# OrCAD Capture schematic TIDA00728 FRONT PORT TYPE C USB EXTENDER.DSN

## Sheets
1 PAGE4: size C; title: Power; rev: A; note: TIDA00728
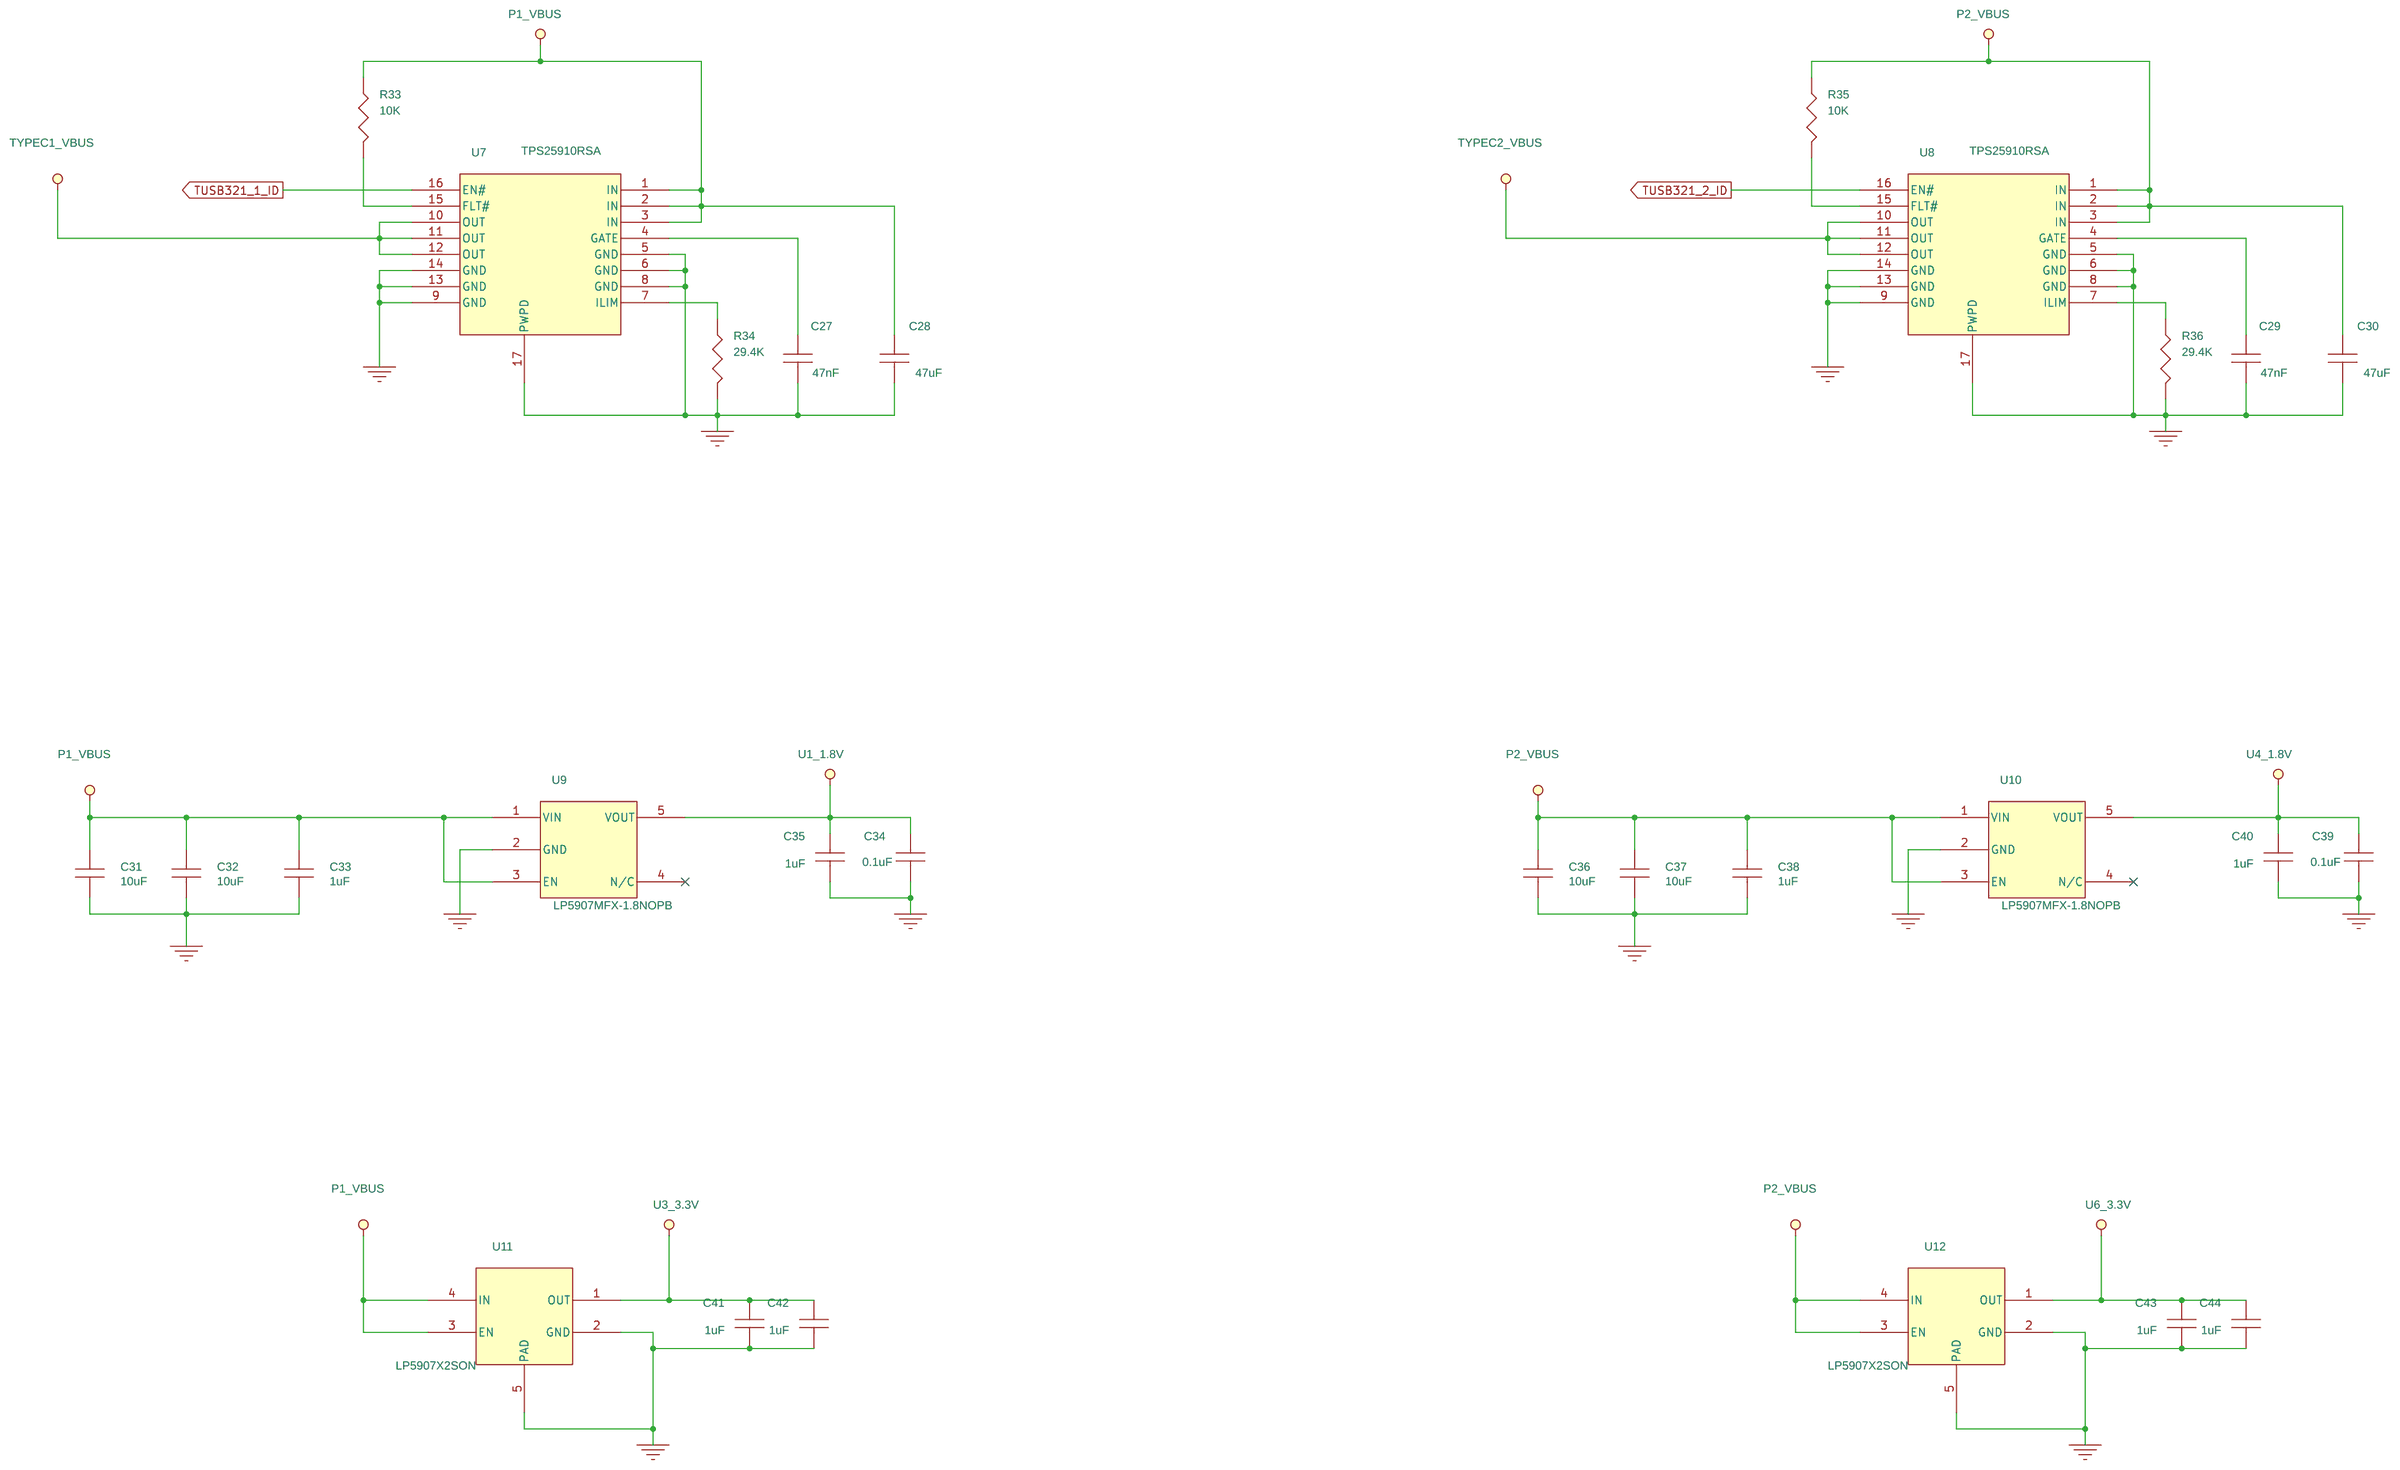
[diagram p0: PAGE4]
2 PAGE3: size C; title: Type C #2
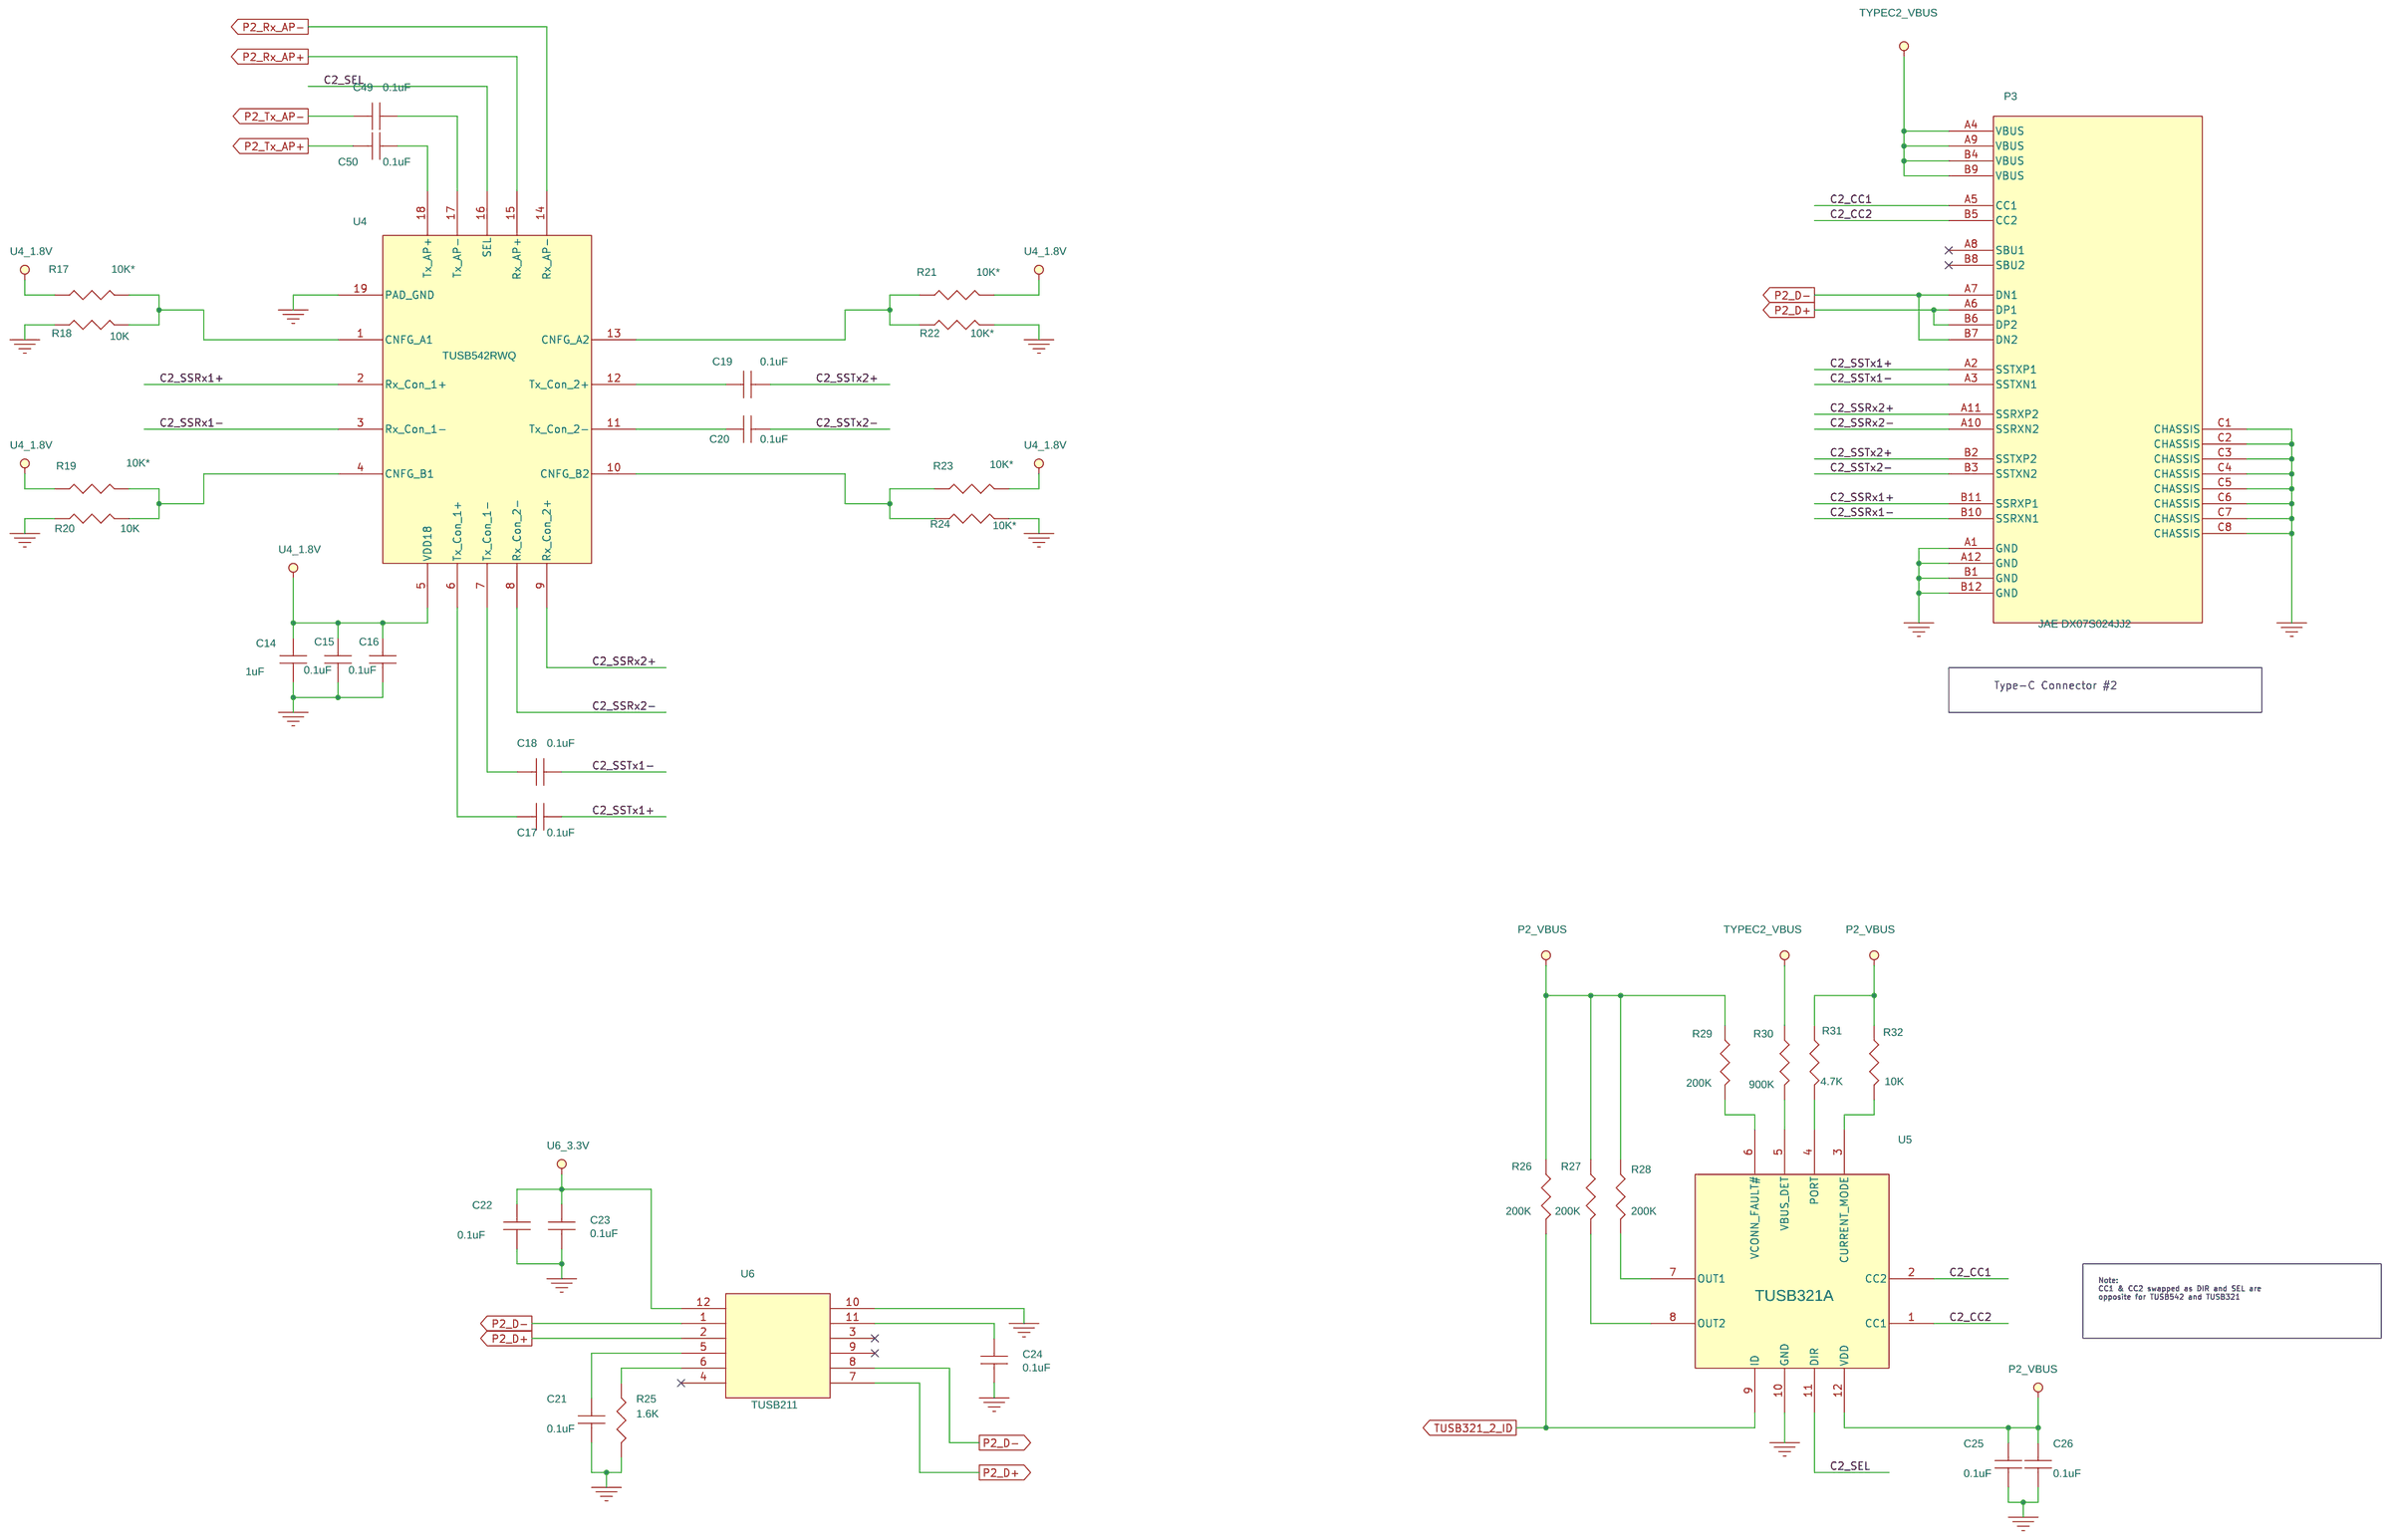
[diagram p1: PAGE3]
3 PAGE2: size C; title: Daughter Card Header + TypeC #1
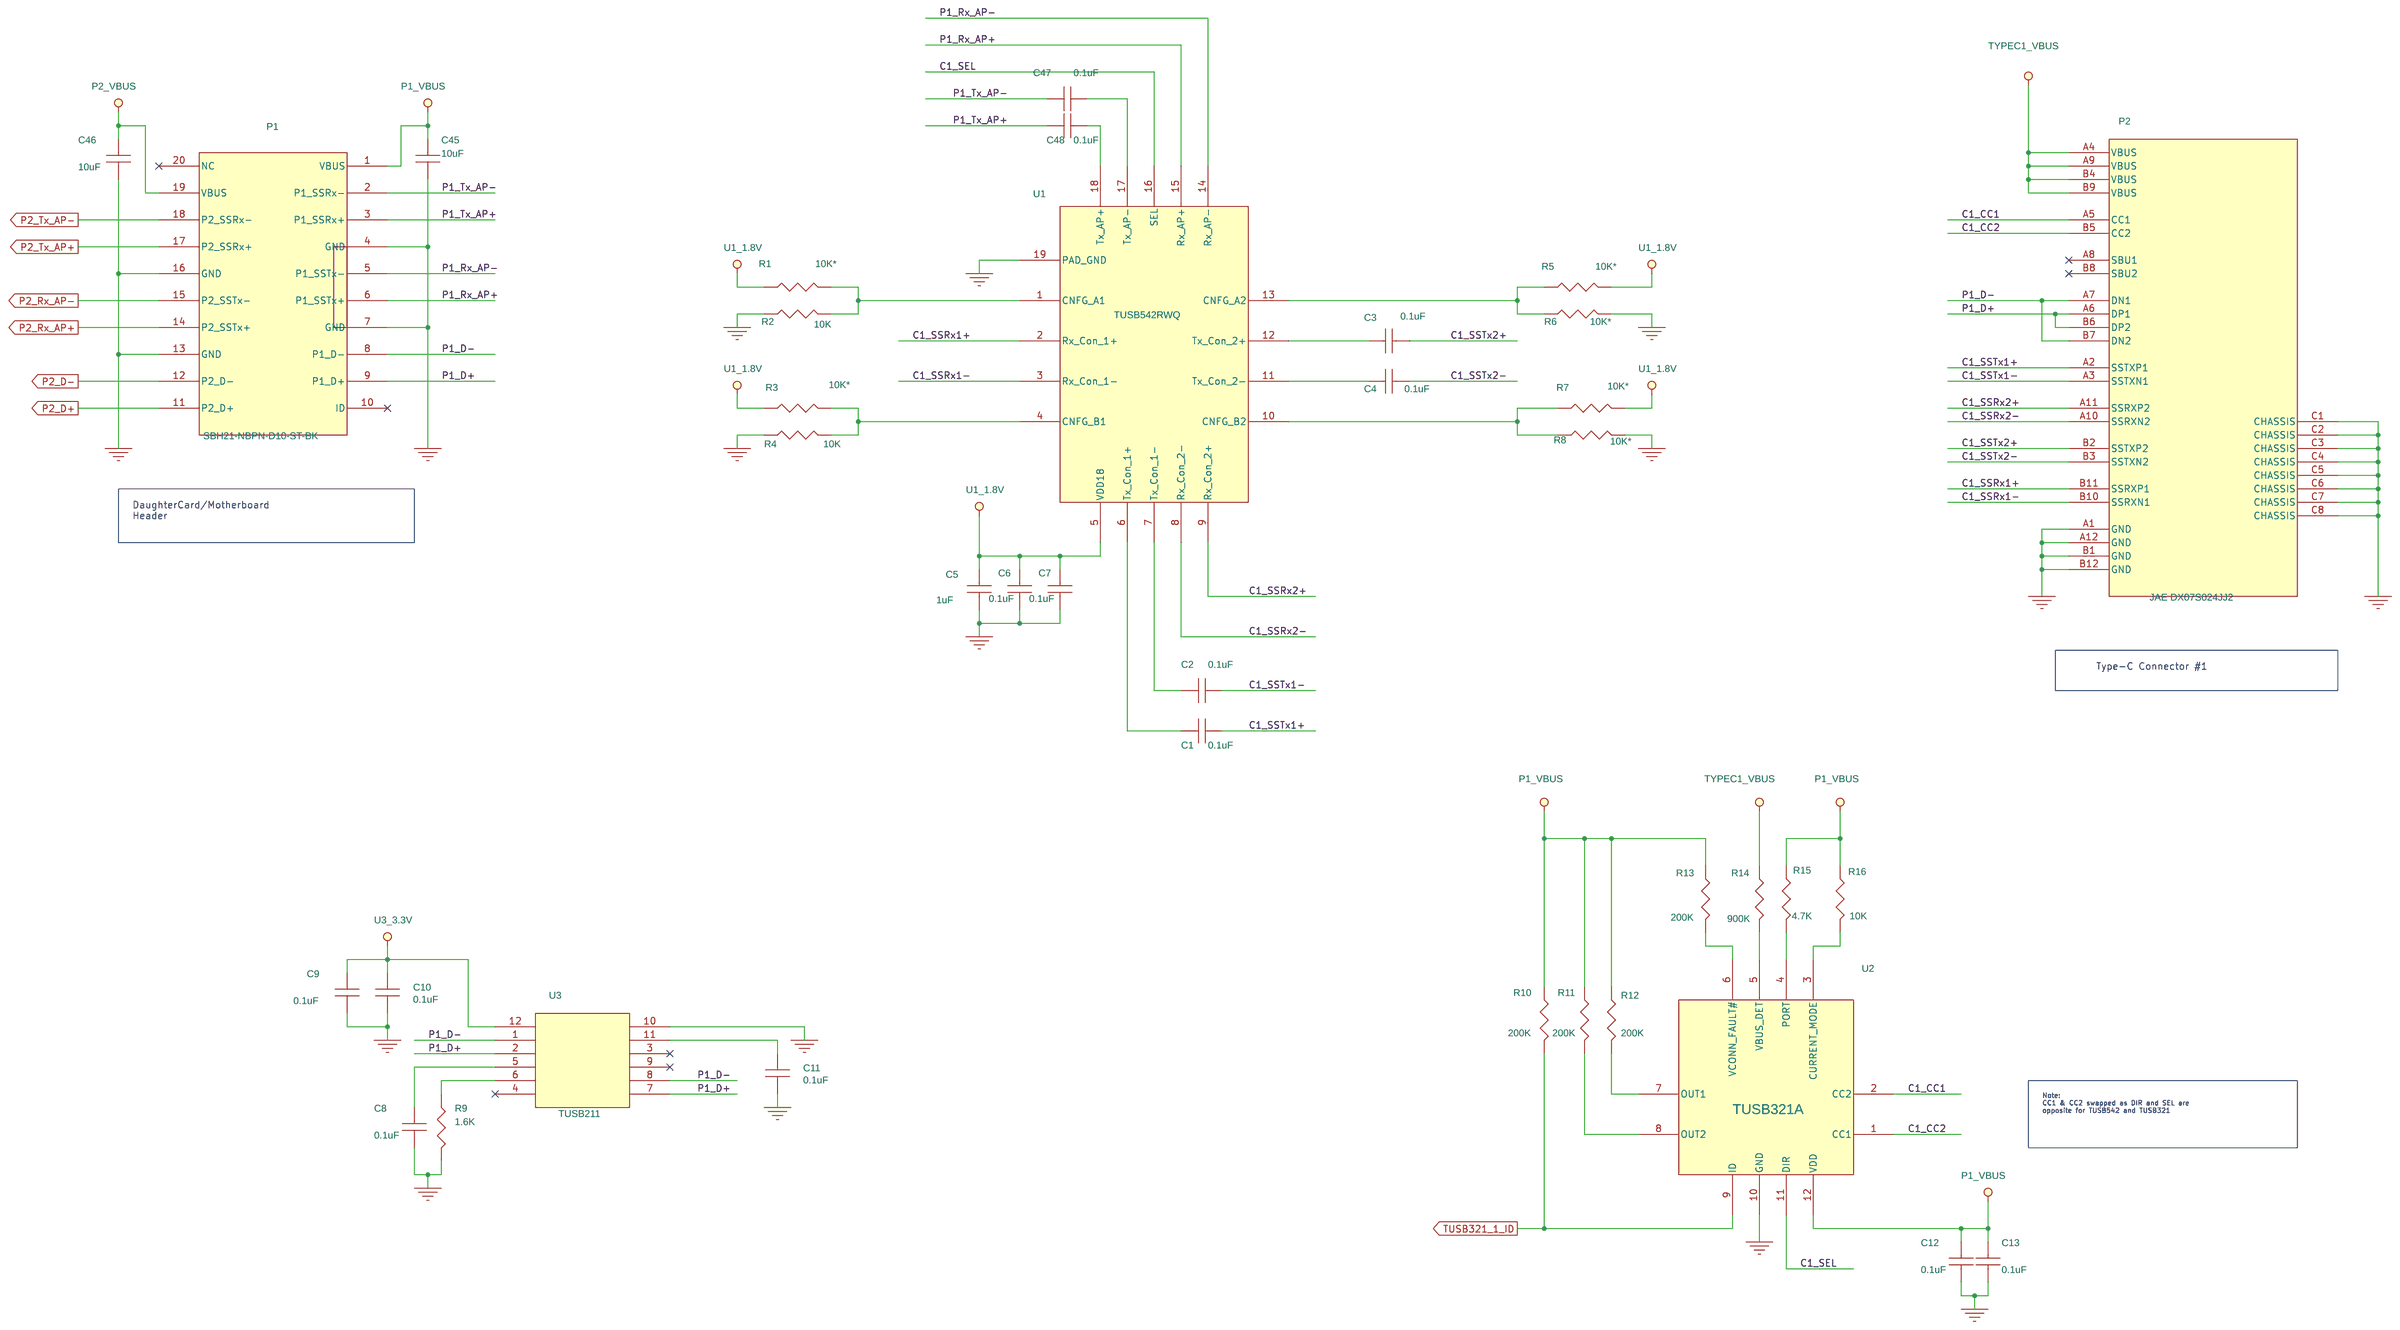
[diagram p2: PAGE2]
4 PAGE1: title: TIDA00728 Front Port Type C USB Extender
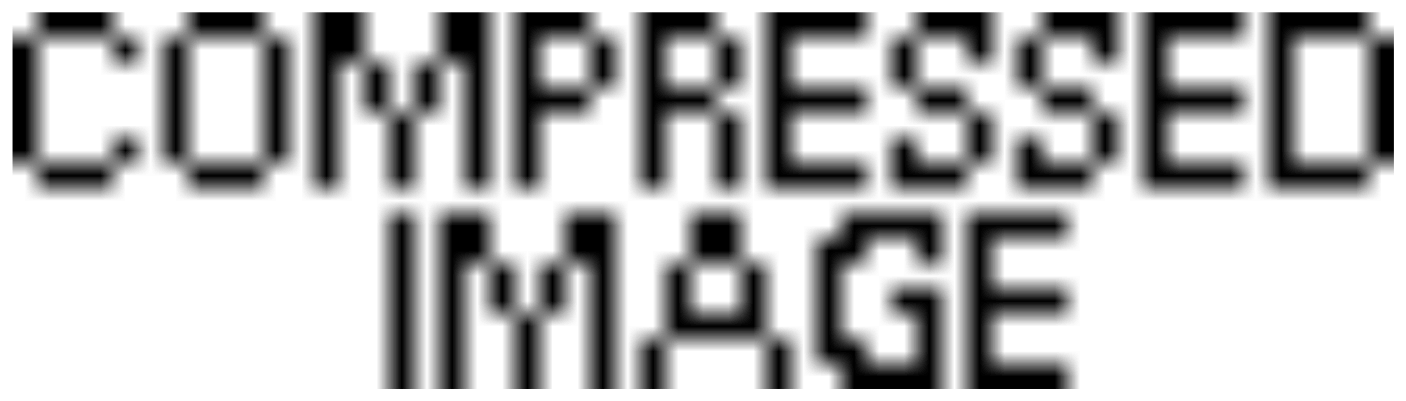
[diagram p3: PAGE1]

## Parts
sheet PAGE2
C1  0.1uF  [0201]
C2  0.1uF  [0201]
C3  0.1uF  [0201]
C4  0.1uF  [0201]
C5  1uF  [0402]
C6  0.1uF  [0201]
C7  0.1uF  [0201]
C8  0.1uF  [0201]
C9  0.1uF  [0201]
C10  0.1uF  [0201]
C11  0.1uF  [0201]
C12  0.1uF  [0201]
C13  0.1uF  [0201]
C45  10uF  [0603]
C46  10uF  [0603]
C47  0.1uF  [0201]
C48  0.1uF  [0201]
P1  SBH21-NBPN-D10-ST-BK  [SBH21-NBPN-D10-ST-BK]
P2  JAE DX07S024JJ2  [typec_jae_topmnt]
R1  10K*  [0402]
R2  10K  [0402]
R3  10K*  [0402]
R4  10K  [0402]
R5  10K*  [0402]
R6  10K*  [0402]
R7  10K*  [0402]
R8  10K*  [0402]
R9  1.6K  [0402]
R10  200K  [0402]
R11  200K  [0402]
R12  200K  [0402]
R13  200K  [0402]
R14  900K  [0402]
R15  4.7K  [0402]
R16  10K  [0402]
U1  TUSB542RWQ  [RWQ]
U2  TUSB321A  [RWB]
U3  TUSB211  [RWB]
sheet PAGE3
C14  1uF  [0402]
C15  0.1uF  [0201]
C16  0.1uF  [0201]
C17  0.1uF  [0201]
C18  0.1uF  [0201]
C19  0.1uF  [0201]
C20  0.1uF  [0201]
C21  0.1uF  [0201]
C22  0.1uF  [0201]
C23  0.1uF  [0201]
C24  0.1uF  [0201]
C25  0.1uF  [0201]
C26  0.1uF  [0201]
C49  0.1uF  [0201]
C50  0.1uF  [0201]
P3  JAE DX07S024JJ2  [typec_jae_topmnt]
R17  10K*  [0402]
R18  10K  [0402]
R19  10K*  [0402]
R20  10K  [0402]
R21  10K*  [0402]
R22  10K*  [0402]
R23  10K*  [0402]
R24  10K*  [0402]
R25  1.6K  [0402]
R26  200K  [0402]
R27  200K  [0402]
R28  200K  [0402]
R29  200K  [0402]
R30  900K  [0402]
R31  4.7K  [0402]
R32  10K  [0402]
U4  TUSB542RWQ  [RWQ]
U5  TUSB321A  [RWB]
U6  TUSB211  [RWB]
sheet PAGE4
C27  47nF  [0402]
C28  47uF  [0402]
C29  47nF  [0402]
C30  47uF  [0402]
C31  10uF  [0603]
C32  10uF  [0603]
C33  1uF  [0402]
C34  0.1uF  [0201]
C35  1uF  [0402]
C36  10uF  [0603]
C37  10uF  [0603]
C38  1uF  [0402]
C39  0.1uF  [0201]
C40  1uF  [0402]
C41  1uF  [0402]
C42  1uF  [0402]
C43  1uF  [0402]
C44  1uF  [0402]
R33  10K  [0402]
R34  29.4K  [0402]
R35  10K  [0402]
R36  29.4K  [0402]
U7  TPS25910RSA  [QFN_16_161x161_26]
U8  TPS25910RSA  [QFN_16_161x161_26]
U9  LP5907MFX-1.8NOPB  [DBV_R-PDSO-G5]
U10  LP5907MFX-1.8NOPB  [DBV_R-PDSO-G5]
U11  LP5907X2SON  [DQN_X2SON_4]
U12  LP5907X2SON  [DQN_X2SON_4]

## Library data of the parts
C1-C4 C8-C13 C17-C26 C47-C50 = cc0201
C5-C7 C14-C16 C27-C30 C33-C35 C38-C44 = cc0402
C31 C32 C36 C37 C45 C46 = cc0603
P1 = USB3_Motherboard_HDR_10X2_M_2mm
P2 P3 = TypeC_JAE_TopMNT_0
R1-R36 = r0402
U1 U4 = TUSB542RWQ
U2 U5 = TUSB321_GPIO
U3 U6 = TUSB211Ref
U7 U8 = TPS25910RSA
U9 U10 = LP5907
U11 U12 = LP5907X2SON

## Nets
GND: C5.2 C6.2 C7.2 C8.2 C9.2 C10.2 C11.2 C12.2 C13.2 C14.2 C15.2 C16.2 C21.2 C22.2 C23.2 C24.2 C25.2 C26.2 C27.2 C28.2 C29.2 C30.2 C31.2 C32.2 C33.2 C34.2 C35.2 C36.2 C37.2 C38.2 C39.2 C40.2 C41.2 C42.2 C43.2 C44.2 C45.2 C46.2 P1.4(GND) P1.7(GND) P1.13(GND) P1.16(GND) P2.A1(GND) P2.A12(GND) P2.B1(GND) P2.B12(GND) P2.C1(CHASSIS) P2.C2(CHASSIS) P2.C3(CHASSIS) P2.C4(CHASSIS) P2.C5(CHASSIS) P2.C6(CHASSIS) P2.C7(CHASSIS) P2.C8(CHASSIS) P3.A1(GND) P3.A12(GND) P3.B1(GND) P3.B12(GND) P3.C1(CHASSIS) P3.C2(CHASSIS) P3.C3(CHASSIS) P3.C4(CHASSIS) P3.C5(CHASSIS) P3.C6(CHASSIS) P3.C7(CHASSIS) P3.C8(CHASSIS) R2.1 R4.1 R6.2 R8.2 R9.2 R18.1 R20.1 R22.2 R24.2 R25.2 R34.2 R36.2 U1.19(PAD_GND) U2.10(GND) U3.10(GND) U4.19(PAD_GND) U5.10(GND) U6.10(GND) U7.5(GND) U7.6(GND) U7.8(GND) U7.9(GND) U7.13(GND) U7.14(GND) U7.17(PWPD) U8.5(GND) U8.6(GND) U8.8(GND) U8.9(GND) U8.13(GND) U8.14(GND) U8.17(PWPD) U9.2(GND) U10.2(GND) U11.2(GND) U11.5(PAD) U12.2(GND) U12.5(PAD)
C1_CC1: P2.A5(CC1) U2.2(CC2)
C1_CC2: P2.B5(CC2) U2.1(CC1)
C1_SEL: U1.16(SEL) U2.11(DIR)
C1_SSRx1+: P2.B11(SSRXP1) U1.2(Rx_Con_1+)
C1_SSRx1-: P2.B10(SSRXN1) U1.3(Rx_Con_1-)
C1_SSRx2+: P2.A11(SSRXP2) U1.9(Rx_Con_2+)
C1_SSRx2-: P2.A10(SSRXN2) U1.8(Rx_Con_2-)
C1_SSTx1+: C1.1 P2.A2(SSTXP1)
C1_SSTx1-: C2.1 P2.A3(SSTXN1)
C1_SSTx2+: C3.2 P2.B2(SSTXP2)
C1_SSTx2-: C4.2 P2.B3(SSTXN2)
C2_CC1: P3.A5(CC1) U5.2(CC2)
C2_CC2: P3.B5(CC2) U5.1(CC1)
C2_SEL: U4.16(SEL) U5.11(DIR)
C2_SSRx1+: P3.B11(SSRXP1) U4.2(Rx_Con_1+)
C2_SSRx1-: P3.B10(SSRXN1) U4.3(Rx_Con_1-)
C2_SSRx2+: P3.A11(SSRXP2) U4.9(Rx_Con_2+)
C2_SSRx2-: P3.A10(SSRXN2) U4.8(Rx_Con_2-)
C2_SSTx1+: C17.1 P3.A2(SSTXP1)
C2_SSTx1-: C18.1 P3.A3(SSTXN1)
C2_SSTx2+: C19.2 P3.B2(SSTXP2)
C2_SSTx2-: C20.2 P3.B3(SSTXN2)
P1_D+: P1.9(P1_D+) P2.A6(DP1) P2.B6(DP2) U3.2(D1P) U3.7(D2P)
P1_D-: P1.8(P1_D-) P2.A7(DN1) P2.B7(DN2) U3.1(D1M) U3.8(D2M)
P1_Rx_AP+: P1.6(P1_SSTx+) U1.15(Rx_AP+)
P1_Rx_AP-: P1.5(P1_SSTx-) U1.14(Rx_AP-)
P1_Tx_AP+: C48.2 P1.3(P1_SSRx+)
P1_Tx_AP-: C47.2 P1.2(P1_SSRx-)
P1_VBUS: C12.1 C13.1 C28.1 C31.1 C32.1 C33.1 C45.1 P1.1(VBUS) R10.1 R11.1 R12.1 R13.1 R15.1 R16.1 R33.1 U2.12(VDD) U7.1(IN) U7.2(IN) U7.3(IN) U9.1(VIN) U9.3(EN) U11.3(EN) U11.4(IN)
P2_D+: P1.11(P2_D+) P3.A6(DP1) P3.B6(DP2) U6.2(D1P) U6.7(D2P)
P2_D-: P1.12(P2_D-) P3.A7(DN1) P3.B7(DN2) U6.1(D1M) U6.8(D2M)
P2_Rx_AP+: P1.14(P2_SSTx+) U4.15(Rx_AP+)
P2_Rx_AP-: P1.15(P2_SSTx-) U4.14(Rx_AP-)
P2_Tx_AP+: C50.2 P1.17(P2_SSRx+)
P2_Tx_AP-: C49.2 P1.18(P2_SSRx-)
P2_VBUS: C25.1 C26.1 C30.1 C36.1 C37.1 C38.1 C46.1 P1.19(VBUS) R26.1 R27.1 R28.1 R29.1 R31.1 R32.1 R35.1 U5.12(VDD) U8.1(IN) U8.2(IN) U8.3(IN) U10.1(VIN) U10.3(EN) U12.3(EN) U12.4(IN)
TUSB321_1_ID: R10.2 U2.9(ID) U7.16(EN#)
TUSB321_2_ID: R26.2 U5.9(ID) U8.16(EN#)
TypeC1_VBUS: P2.A4(VBUS) P2.A9(VBUS) P2.B4(VBUS) P2.B9(VBUS) R14.1 U7.10(OUT) U7.11(OUT) U7.12(OUT)
TypeC2_VBUS: P3.A4(VBUS) P3.A9(VBUS) P3.B4(VBUS) P3.B9(VBUS) R30.1 U8.10(OUT) U8.11(OUT) U8.12(OUT)
U1_1.8V: C5.1 C6.1 C7.1 C34.1 C35.1 R1.1 R3.1 R5.2 R7.2 U1.5(VDD18) U9.5(VOUT)
U3_3.3V: C9.1 C10.1 C41.1 C42.1 U3.12(VCC) U11.1(OUT)
U4_1.8V: C14.1 C15.1 C16.1 C39.1 C40.1 R17.1 R19.1 R21.2 R23.2 U4.5(VDD18) U10.5(VOUT)
U6_3.3V: C22.1 C23.1 C43.1 C44.1 U6.12(VCC) U12.1(OUT)
N16593198: C3.1 U1.12(Tx_Con_2+)
N16593202: C4.1 U1.11(Tx_Con_2-)
N16594439: R1.2 R2.2 U1.1(CNFG_A1)
N16594463: R3.2 R4.2 U1.4(CNFG_B1)
N16594907: R5.1 R6.1 U1.13(CNFG_A2)
N16594998: R7.1 R8.1 U1.10(CNFG_B2)
N16595743: C2.2 U1.7(Tx_Con_1-)
N16595815: C1.2 U1.6(Tx_Con_1+)
N16596805: R9.1 U3.6(EQ)
N16596896: C8.1 U3.5(RSTN)
N16597097: C11.1 U3.11(VREG)
N16601587: R12.2 U2.7(OUT1)
N16601594: R11.2 U2.8(OUT2)
N16601612: R13.2 U2.6(VCONN_FAULT#)
N16601624: R14.2 U2.5(VBUS_DET)
N16601628: R15.2 U2.4(PORT)
N16601632: R16.2 U2.3(CURRENT_MODE)
N16603119: R17.2 R18.2 U4.1(CNFG_A1)
N16603151: R19.2 R20.2 U4.4(CNFG_B1)
N16603309: R21.1 R22.1 U4.13(CNFG_A2)
N16603349: R23.1 R24.1 U4.10(CNFG_B2)
N16603377: C18.2 U4.7(Tx_Con_1-)
N16603385: C17.2 U4.6(Tx_Con_1+)
N16603499: C50.1 U4.18(Tx_AP+)
N16603509: C49.1 U4.17(Tx_AP-)
N16603551: C19.1 U4.12(Tx_Con_2+)
N16603555: C20.1 U4.11(Tx_Con_2-)
N16604854: R25.1 U6.6(EQ)
N16604882: C21.1 U6.5(RSTN)
N16604934: C24.1 U6.11(VREG)
N16605800: R28.2 U5.7(OUT1)
N16605808: R27.2 U5.8(OUT2)
N16605824: R29.2 U5.6(VCONN_FAULT#)
N16605836: R30.2 U5.5(VBUS_DET)
N16605840: R31.2 U5.4(PORT)
N16605844: R32.2 U5.3(CURRENT_MODE)
N16608365: R33.2 U7.15(FLT#)
N16608664: R34.1 U7.7(ILIM)
N16608671: C27.1 U7.4(GATE)
N16609533: R35.2 U8.15(FLT#)
N16609671: R36.1 U8.7(ILIM)
N16609679: C29.1 U8.4(GATE)
N16623389: C48.1 U1.18(Tx_AP+)
N16623398: C47.1 U1.17(Tx_AP-)

Not connected (* = marked no-connect by the designer): P1 10(ID)* 20(NC)*; P2 A8(SBU1)* B8(SBU2)*; P3 A8(SBU1)* B8(SBU2)*; U3 3(TEST)* 4(CD)* 9(ENA_HS)*; U6 3(TEST)* 4(CD)* 9(ENA_HS)*; U9 4(N/C)*; U10 4(N/C)*

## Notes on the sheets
sheet 2
- Type-C Connector #2
- Note:
  CC1 & CC2 swapped as DIR and SEL are
  opposite for TUSB542 and TUSB321
sheet 3
- DaughterCard/Motherboard
  Header
- Type-C Connector #1
- Note:
  CC1 & CC2 swapped as DIR and SEL are
  opposite for TUSB542 and TUSB321
